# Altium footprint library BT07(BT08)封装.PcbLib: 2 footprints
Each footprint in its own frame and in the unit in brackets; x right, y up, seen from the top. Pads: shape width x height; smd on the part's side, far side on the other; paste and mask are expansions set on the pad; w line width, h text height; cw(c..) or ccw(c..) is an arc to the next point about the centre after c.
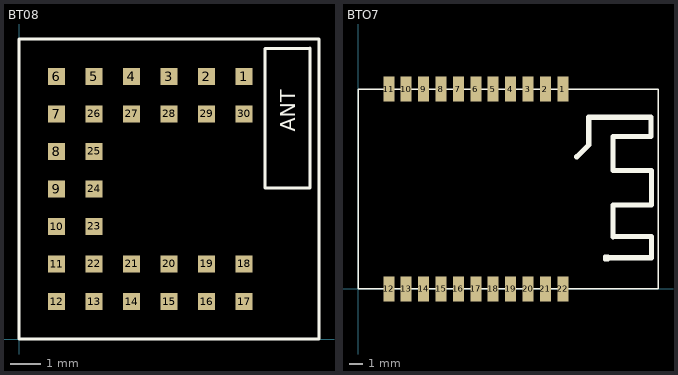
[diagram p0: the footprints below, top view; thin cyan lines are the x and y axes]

## BT08 [mm]
pads (30):
  rect 0.58x0.58 smd: 1(7.5,8.75) 2(6.25,8.75) 3(5,8.75) 4(3.75,8.75) 5(2.5,8.75) 6(1.25,8.75) 7(1.25,7.5) 8(1.25,6.25) 9(1.25,5) 10(1.25,3.75) 11(1.25,2.5) 12(1.25,1.25) 13(2.5,1.25) 14(3.75,1.25) 15(5,1.25) 16(6.25,1.25) 17(7.5,1.25) 18(7.5,2.5) 19(6.25,2.5) 20(5,2.5) 21(3.75,2.5) 22(2.5,2.5) 23(2.5,3.75) 24(2.5,5) 25(2.5,6.25) 26(2.5,7.5) 27(3.75,7.5) 28(5,7.5) 29(6.25,7.5) 30(7.5,7.5)
Top Overlay:
  lines w0.1: 9.449,5.029 9.7,5.029 9.7,9.7 ; 9.574,5.029 8.204,5.029 8.204,9.677 9.7,9.677 ; 0,0 0,10 10,10 10,0 0,0
  text "ANT" at 9.216,6.903 h0.5

## BTO7 [mm] "Stamp holes"
height 1
pads (22):
  rect 0.8x1.8 smd: 1(14.95,14.6) 2(13.68,14.6) 3(12.41,14.6) 4(11.14,14.6) 5(9.87,14.6) 6(8.6,14.6) 7(7.33,14.6) 8(6.06,14.6) 9(4.79,14.6) 10(3.52,14.6) 11(2.25,14.6) 12(2.25,0) 13(3.52,0) 14(4.79,0) 15(6.06,0) 16(7.33,0) 17(8.6,0) 18(9.87,0) 19(11.14,0) 20(12.41,0) 21(13.68,0) 22(14.95,0)
Top Overlay:
  lines w0.1: 0,0 0,14.6 21.9,14.6 21.9,0 0,0
  lines w0.254: 18.268,2.15 18.014,2.15 18.014,2.404 18.268,2.404
  lines w0.381: 15.977,9.652 16.846,10.522 16.846,10.783 16.846,12.538 21.393,12.538 21.393,11.141 18.624,11.141 18.624,8.652 21.418,8.651 21.418,6.137 18.624,6.137 ; 18.141,2.277 21.418,2.277 ; 18.612,3.82 18.612,6.131 ; 18.624,3.825 21.418,3.825 ; 21.418,2.276 21.418,3.826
